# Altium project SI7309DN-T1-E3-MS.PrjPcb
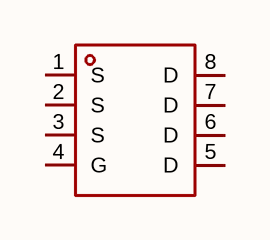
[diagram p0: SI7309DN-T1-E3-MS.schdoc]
1 sheet, 1 parts. Net scope: global (net labels, ports and power ports of the same name join across sheets).

## Sheet SI7309DN-T1-E3-MS.schdoc
size 127 x 101 mm

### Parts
Q?  si7309dn-t1-e3-ms  [POWERPAK-1212-8_L3.0-W3.0-P0.65-LS3.3-BL]  (value not drawn)

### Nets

Not connected (* = marked no-connect by the designer): Q? 1(S) 2(S) 3(S) 4(G) 5(D) 6(D) 7(D) 8(D)

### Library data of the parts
Q? = si7309dn-t1-e3-ms: 数量:1个P沟道;漏源电压(Vdss):60V;连续漏极电流(Id):20A;导通电阻(RDS(on)):49mΩ@10V;耗散功率(Pd):25W;阈值电压(Vgs(th)):1.2V;; Manufacturer: MSKSEMI(美森科); AddInBom: yes; ModelId: 74fc8db97a8d4d328d7f3b4acba39a5e; ModelTransform: 129.921,129.921,0,0,0,0,0,0,0; Number: 1个P沟道; Drain to Source Voltage: 60V; Current - Continuous Drain(Id): 20A; Pd - Power Dissipation: 25W; Gate Threshold Voltage (Vgs(th)): 1.2V; Gate Charge(Qg): 6.1nC; Input Capacitance(Ciss): 585pF; Reverse Transfer Capacitance (Crss@Vds): 85pF; Type: P沟道; Output Capacitance(Coss): 100pF; Vgs: ±20V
